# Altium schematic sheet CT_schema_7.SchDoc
size 369 x 243 mm
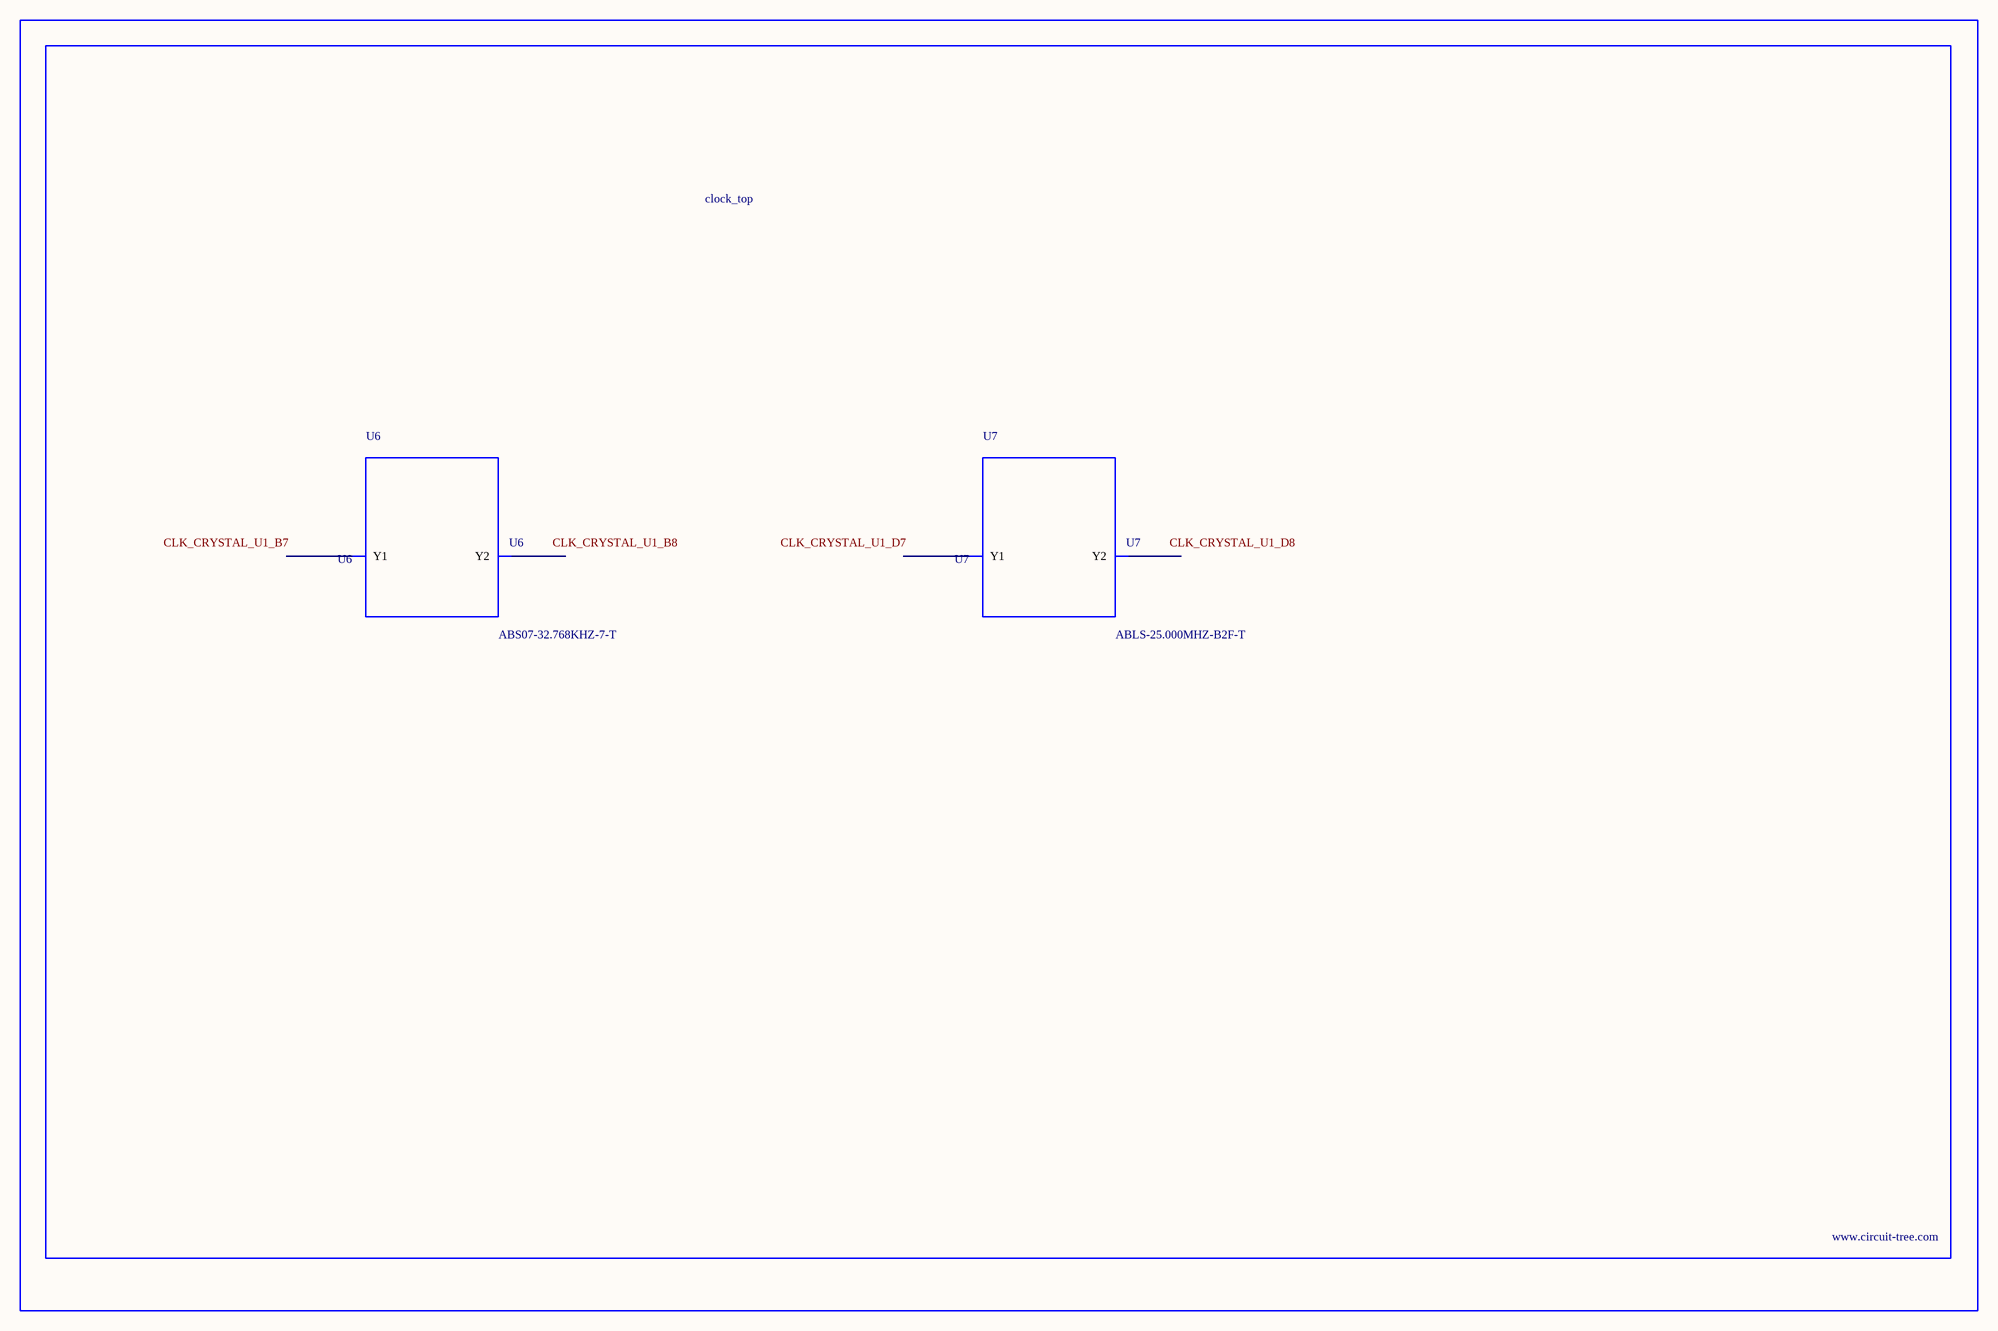
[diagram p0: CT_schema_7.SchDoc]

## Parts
BORDER6  (no value)
U6  ABS07-32.768KHZ-7-T  [ABS07-32.768KHZ-7-T]
U7  ABLS-25.000MHZ-B2F-T  [ABLS-25.000MHZ-B2F-T]

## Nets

Not connected (* = marked no-connect by the designer): U6 1(Y1) 2(Y2); U7 1(Y1) 2(Y2)

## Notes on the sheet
- Labels drawn without touching a wire or pin: CLK_CRYSTAL_U1_B7, CLK_CRYSTAL_U1_B8, CLK_CRYSTAL_U1_D7, CLK_CRYSTAL_U1_D8

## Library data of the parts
BORDER6 = BORDER_PAGE6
